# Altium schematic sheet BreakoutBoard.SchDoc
size B
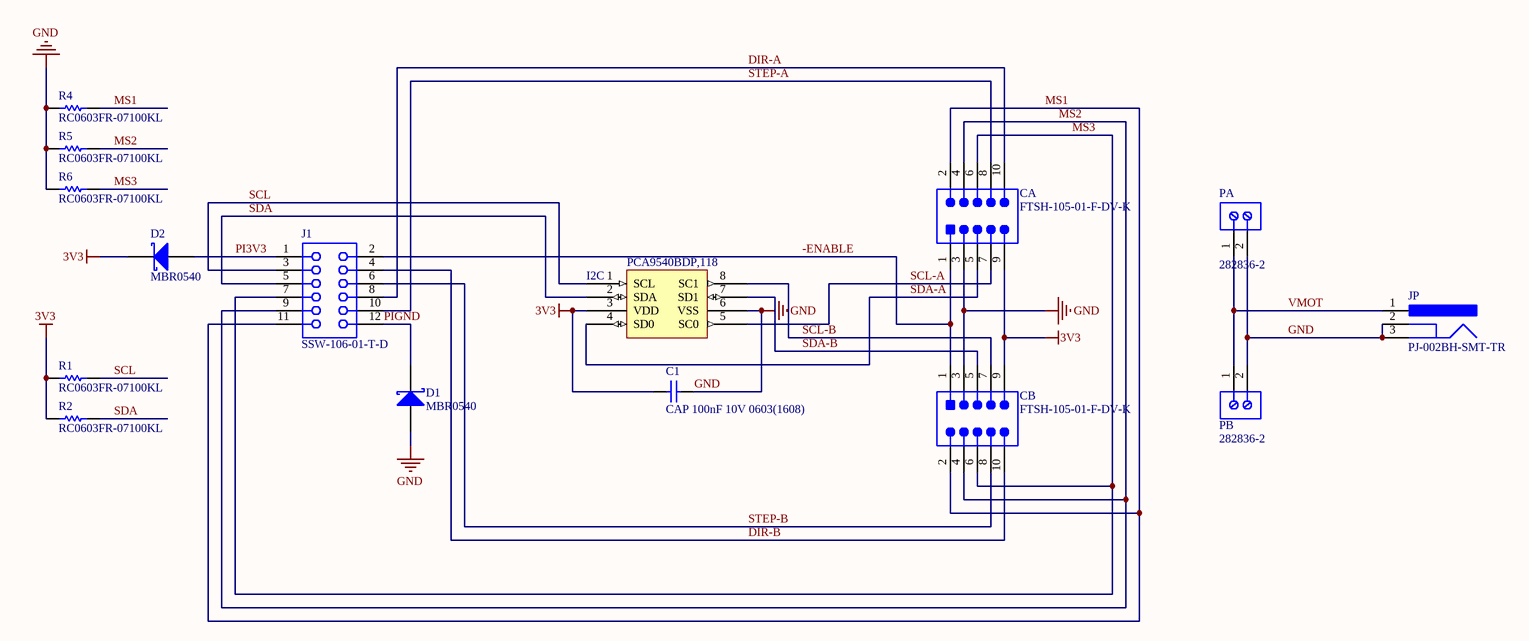
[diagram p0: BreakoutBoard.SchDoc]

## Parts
C1  CAP 100nF 10V 0603(1608)  [CAPC0603(1608)100_M]
CA  FTSH-105-01-F-DV-K  [SMTC-FTSH-105-01-L-DV-K_V]
CB  FTSH-105-01-F-DV-K  [SMTC-FTSH-105-01-L-DV-K_V]
D1  MBR0540  [FAIR-SOD123-2_V]
D2  MBR0540  [FAIR-SOD123-2_V]
I2C  PCA9540BDP,118  [TSOP65P490X110-8N]
J1  SSW-106-01-T-D  [SMTC-SSW-106-01-X-D]
JP  PJ-002BH-SMT-TR  [CUI-PJ-002BH-SMT_V]
PA  282836-2  [TECO-282836-2_V]
PB  282836-2  [TECO-282836-2_V]
R1  RC0603FR-07100KL  [RESC1608X55X25ML10T15]
R2  RC0603FR-07100KL  [RESC1608X55X25ML10T15]
R4  RC0603FR-07100KL  [RESC1608X55X25ML10T15]
R5  RC0603FR-07100KL  [RESC1608X55X25ML10T15]
R6  RC0603FR-07100KL  [RESC1608X55X25ML10T15]

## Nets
3V3: C1.1 CA.9 CB.9 D2.2(K) I2C.3(VDD) R1.1 R2.1
GND: C1.2 CA.3 CB.3 D1.1(A) I2C.6(VSS) JP.2 JP.3 PA.2 PB.2 R4.1 R5.1 R6.1
-ENABLE: CA.1 CB.1 J1.2
DIR-A: CA.10 J1.8
DIR-B: CB.10 J1.4
MS1: CA.2 CB.2 J1.11 R4.2
MS2: CA.4 CB.4 J1.9 R5.2
MS3: CA.6 CB.6 J1.7 R6.2
PI3V3: D2.1(A) J1.1
PIGND: D1.2(K) J1.12
SCL: I2C.1(SCL) J1.3 R1.2
SCL-A: CA.7 I2C.5(SC0)
SCL-B: CB.7 I2C.8(SC1)
SDA: I2C.2(SDA) J1.5 R2.2
SDA-A: CA.5 I2C.4(SD0)
SDA-B: CB.5 I2C.7(SD1)
STEP-A: CA.8 J1.10
STEP-B: CB.8 J1.6
VMOT: JP.1 PA.1 PB.1

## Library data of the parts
C1 = CMP-1035-02580-1: CAP 100nF 10V ±10% 0603 (1608 Metric) Thickness 1mm SMD; Tolerance: Â±10%; Case-EIA: 0603; Case-Metric: 1608
CA CB = CMP-2000-05352-1: Male Header, Pitch 1.27 mm, 2 x 5 Position, Height 6.12 mm, RoHS, Tube; Manufacturer: Samtec; Number of Positions: 10; Connector Type: Header,Shrouded; Number of Positions Loaded: All; Row Spacing: 0.050"(1.27mm); System: Connector
D1 D2 = CMP-2000-05114-1: Schottky Rectifier, 40 V, 0.5 A, 2-Pin SOD-123, RoHS, Tape and Reel; Manufacturer: Fairchild; Speed: FastRecovery=200mA(Io); Voltage - DC Reverse (Vr) (Max): 40V; Online Catalog: SchottkyDiode; Voltage - Forward (Vf) (Max) @ If: 510mV@500mA; Current - Reverse Leakage @ Vr: 20µA@40V; Current - Average Rectified (Io): 500mA; Other Names: MBR0540CT
I2C = CMP-00893-4: IC I2C MUX 2CH 8-TSSOP; Logic Function: Multiplexer; Max Frequency: 400kHz; Max Power Dissipation: 400mW; Max Supply Voltage: 5.5V; Min Supply Voltage: 2.3V; Nominal Supply Current: 100mA; Number of Channels: 2; Number of Input Lines: 1; On-State Resistance: 55R; Propagation Delay: 0.3ns; Quiescent Current: 65uA
J1 = CMP-1023-00356-1: SQ Post Socket, Through-hole, Vertical, -55 to 105 degC, 2.54mm Pitch, 12-Pin, Female, RoHS; Manufacturer: Samtec
JP = CMP-2000-06897-1: DC Power Jack, 24 V, -25 to 85 degC, 3-Pin SMD, RoHS, Bulk; Manufacturer: CUIInc.; Brand: CUI; Insulation Resistance: 100MOhms; Inside Contact Diameter: 2.5mm; Outside Contact Diameter: 6.5mm; Voltage Rating: 24V; Current Rating: 5A; Mounting Angle: Right
PA PB = CMP-1684-00017-1: Female Header, Pitch 5 mm, 1 x 2 Position, Height 10 mm, Tail Length 3.5 mm, Rohs, Bulk; Manufacturer: TE Connectivity; Wire Gauge: 16-30AWG; Product Training Modules: Wire-to-BoardEurostyleTerminalBlocks; Clamp Material - Plating: Brass-NickelPlated; Voltage: 300V; Mating Orientation: HorizontalwithBoard; Current: 13.5A; Pitch: 0.197"(5.00mm); Screw Thread: M3; 3D Model: 282836-2.pdf; Other Names: 5ULV-02B / A98076; Dynamic Catalog: BuchananSeries; Number of Levels: 1; Torque - Screw: 0.68Nm(6Lb-In); Featured Product: EurostyleTerminalBlockConnectors; Positions Per Level: 2; Wire Termination: Screw-RisingCageClamp; System: Connector
R1 R2 R4-R6 = CMP-2100-03662-1: Chip Resistor, 100 KOhm, +/- 1%, 0.1 W, -55 to 155 degC, 0603 (1608 Metric), RoHS, Tape and Reel; Manufacturer: Yageo; Power Rating: 100mW; Voltage Rating: 50V; Temperature Coefficient: 100ppm/degreesC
